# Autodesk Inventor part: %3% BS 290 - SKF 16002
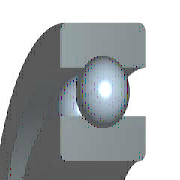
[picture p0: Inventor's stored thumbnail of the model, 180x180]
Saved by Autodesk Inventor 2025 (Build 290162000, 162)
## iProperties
Created: 2024-01
Part Number: %3% BS 290 - SKF 16002
Material: Acciaio, Dolce
Description: Cuscinetti a sfere a fila singola
Document SubType Name: Modeling
Standard: BS 290
Designer: Ryzen5700u
Standards Organization: BSI
Language: it-IT
Size Designation: SKF 16002
Categories: <MemberInstance><Categories><Category DisplayName="Parti albero" InternalName="7f7aeb1f-a693-4053-b835-cee3144e0d98" Mnemonic="SHFT"><Category DisplayName="Cusc
Density: 7.85 g/cm^3
Appearance: Semilucidato
IsCustomPart: 0
Author: Ryzen5700u
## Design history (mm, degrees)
node "WorkPoint1"
node "WorkAxis1"
node "WorkPlane3"
node "WorkPlane4"
node "WorkPoint2"
pattern_circular "Seriepolare1" dims "d17" = 73.11765 (= msp_pocet), angle "d19" = 360 deg
body "Solid1"
node "Schizzo1"
revolve "Rivoluzione1" stored, may be unused: angle "d6" = 360 deg
revolve "Rivoluzione2" stored, may be unused: angle "d10" = 360 deg
node "Schizzo4"
revolve "Rivoluzione3" stored, may be unused: angle "d16" = 360 deg
fillet "Raccordo1" dims "d20" = 0.3 (= r)
sketch "Schizzo2"
  geometry: L1 (7.5, 8)-(16, 8); L2 (7.5, 0)-(7.5, 8); L3 (16, 0)-(7.5, 0); L4 (16, 8)-(16, 0); L5 (0, 0)-(0, 20); L6 (0, 0)-(0, 20); L7 (-7.2, 0)-(43.2, 0) reference
  constraints: 12 end point, 3 vertical, 2 horizontal, 1 collinear, 1 other
  dimensions: "d1" = 15 diameter of L1.start L5 (= Diam); "d3" = 32 diameter of L1.end L5 (= DD); "d5" = 8 distance of L2.start L1.start (= msp_mdtd2)
sketch "Schizzo3"
  geometry: L1 (13.28, 8)-(13.28, 6.04); L2 (10.22, 8)-(13.28, 8); L3 (10.22, 6.04)-(10.22, 8); L4 (10.22, 0)-(10.22, 1.96); L5 (13.28, 0)-(10.22, 0); L6 (13.28, 1.96)-(13.28, 0); L7 (16, 0)-(-16, 0) reference; L8 (16, 8)-(-16, 8) reference; L9 (0, -42.29)-(0, 61.29); L10 (0, 82.007)-(0, -63.007) reference; A1 r 2.55 centre (11.75, 4) between (13.28, 1.96) and (13.28, 6.04); A2 r 2.55 centre (11.75, 4) between (10.22, 6.04) and (10.22, 1.96)
  constraints: 14 end point, 4 collinear, 4 point on circle, 4 vertical, 2 centre point, 2 concentric, 2 horizontal, 2 point on line
  dimensions: "d9" = 5.1 diameter of A1 (= msp_mdtd6); "d21" = 10.22 distance between parallel lines of L9 L4 (= 0.5 x msp_d1); "d22" = 11.75 distance from line of L9 A1.centre (= 0.5 x msp_ds); "d23" = 13.28 distance between parallel lines of L9 L6 (= 0.5 x msp_dd1)
sketch "Schizzo5"
  geometry: L1 (11.75, 1.45)-(11.75, 6.55); L2 (13.28, 0)-(-13.28, 0) reference; L3 (11.75, 1.45)-(11.75, 6.55); A1 r 2.55 centre (11.75, 4) between (11.75, 1.45) and (11.75, 6.55); A2 r 2.55 centre (11.75, 4) between (13.28, 1.96) and (13.28, 6.04) reference
  constraints: 4 end point, 2 point on circle, 1 centre point, 1 concentric, 1 vertical
  dimensions: "d13" = 0 horizontal distance of A1.centre L1.start; "d15" = 5.1001 diameter of A1 (computed from msp_mdtd6)
other parameters: "Diam" = 15 [user parameter; used in 3 equation terms], "DD" = 32 [user parameter; used in 3 equation terms], "B" = 8 [user parameter; used in 1 equation term], "r" = 0.3 [user parameter; used in 1 equation term], "msp_ds" = 23.5 (= 0.5 x Diam + 0.5 x DD) [user parameter; used in 5 equation terms], "msp_d0" = 5.1 (= -0.3 x Diam + 0.3 x DD) [user parameter; used in 4 equation terms], "msp_d1" = 20.44 (= msp_ds - 0.6 x msp_d0) [user parameter; used in 1 equation term], "msp_dd1" = 26.56 (= msp_ds + 0.6 x msp_d0) [user parameter; used in 1 equation term], "msp_pom" = 35.25 (= 1.5 x msp_ds) [user parameter; used in 1 equation term], "msp_mdtd2" = 8 (= B) [user parameter; used in 3 equation terms], "msp_mdtd4" = 23.5 (= msp_ds) [user parameter], "msp_mdtd6" = 5.1 (= msp_d0) [user parameter; used in 2 equation terms], "msp_mdtd7" = 4 (= 0.5 x msp_mdtd2) [user parameter], "msp_pocet" = 73.11765 (computed from msp_d0, msp_pom) [user parameter; used in 1 equation term], "d2" = 72 (derived), "d4" = 19 (derived), "d7" = 0, "d8" = 15.6 (derived), "d11" = -8 (computed from msp_mdtd2), "d12" = 0 (derived), "d14" = 15.6001 (derived), "d26" = 0, "d27" = 0, "d28" = 0, "d29" = 0, "d30" = 0
